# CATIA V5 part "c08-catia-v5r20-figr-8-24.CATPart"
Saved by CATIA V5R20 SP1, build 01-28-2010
Part number: Part1
Bounding box of the stored display mesh (mm): x -50 to 50, y -62.5 to 62.5, z 0 to 10
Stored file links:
  D:\v5_r20\psrt_files_downloaded\c08-catia-v5r20-prt\c08-catia-v5r20-figr-8-24.CATPart
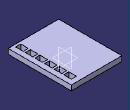
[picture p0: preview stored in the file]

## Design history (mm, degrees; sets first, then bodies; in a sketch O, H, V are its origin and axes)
Body1 (main body)
  Sketch1 on xy-plane, origin (0, 0, 0), H (1, 0, 0), V (0, 1, 0)
    line L1 (-50, 62.5) -> (50, 62.5)
    line L2 (50, 62.5) -> (50, -62.5)
    line L3 (50, -62.5) -> (-50, -62.5)
    line L4 (-50, -62.5) -> (-50, 62.5)
    axis line L5 (50, -62.5) -> (-50, 62.5)
    length L3 = 100
    length L2 = 125
    horizontal: L1 H, L3 H
    vertical: L2 V, L4 V
    midpoint: O L5
  Pad1: profile Sketch1, direction (0, 0, 1), length 10
  Sketch2 on face of Pad1, origin (0, 0, 10), H (1, 0, 0), V (0, 1, 0)
    line L1 (40, -57.5) -> (30, -57.5)
    line L2 (30, -57.5) -> (30, -42.5)
    line L3 (30, -42.5) -> (40, -42.5)
    line L4 (40, -42.5) -> (40, -57.5)
    reference projected line E1 (-50, -62.5) -> (50, -62.5) from edge [face of Pad1 | face of Pad1]
    reference projected line E2 (50, -62.5) -> (50, 62.5) from edge [face of Pad1 | face of Pad1]
    length L1 = 10
    length L4 = 15
    distance L1 E1 = 5
    distance L4 E2 = 10
    horizontal: L1 H, L3 H
    vertical: L2 V, L4 V
  Pocket1: profile Sketch2, direction (0, 0, -1), through (limit type 3)
  RectPattern1: of Pocket1, direction 1 instances 6, spacing 19, along edge [face of Pad1 | face of Pad1], direction 2 instances 6, spacing 15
